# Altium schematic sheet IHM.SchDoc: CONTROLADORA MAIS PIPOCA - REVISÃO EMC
size A3; DocumentNumber: GA0050; SheetNumber: 9; SheetTotal: 17
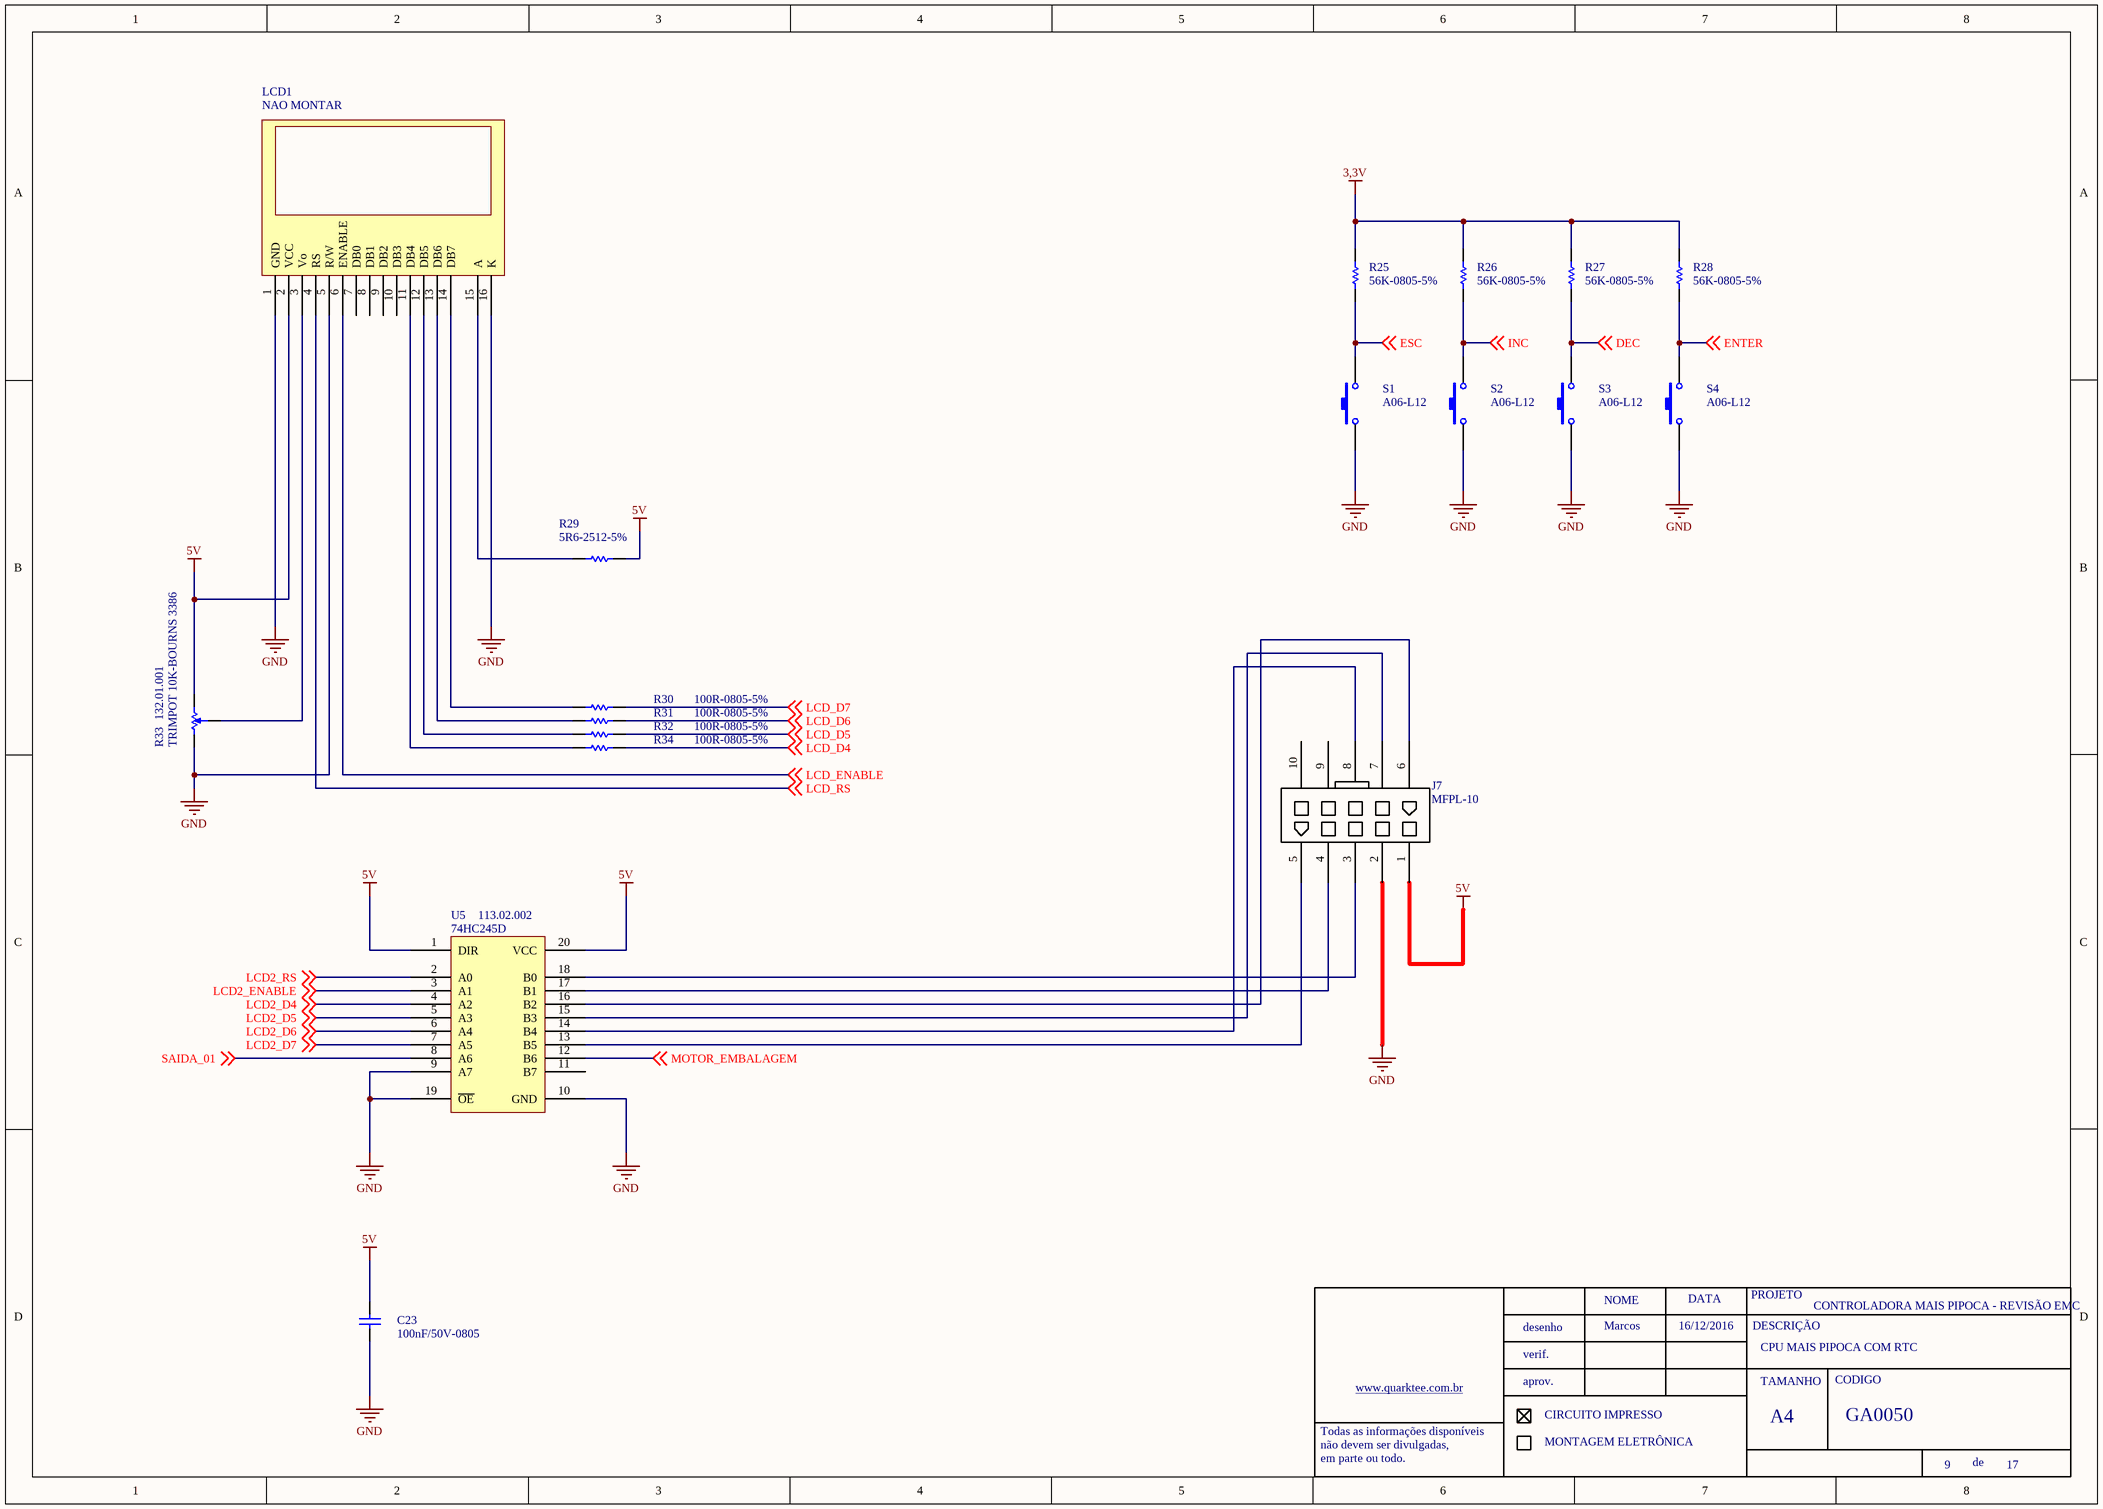
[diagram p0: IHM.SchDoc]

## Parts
C23  100nF/50V-0805  [0805-REVISADO ONDA]
J7  MFPL-10
LCD1  NAO MONTAR  [WH1602B_DS]
R25  56K-0805-5%  [0805-REVISADO ONDA]
R26  56K-0805-5%  [0805-REVISADO ONDA]
R27  56K-0805-5%  [0805-REVISADO ONDA]
R28  56K-0805-5%  [0805-REVISADO ONDA]
R29  5R6-2512-5%  [2512 - REVISADO ONDA]
R30  100R-0805-5%  [0805-REVISADO ONDA]
R31  100R-0805-5%  [0805-REVISADO ONDA]
R32  100R-0805-5%  [0805-REVISADO ONDA]
R33  TRIMPOT 10K-BOURNS 3386  ERP: 132.01.001  [TRIMPOT 3386]
R34  100R-0805-5%  [0805-REVISADO ONDA]
S1  A06-L12  [CHAVE_A06]
S2  A06-L12  [CHAVE_A06]
S3  A06-L12  [CHAVE_A06]
S4  A06-L12  [CHAVE_A06]
U5  74HC245D  ERP: 113.02.002  [SOIC-20]

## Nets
3,3V: R25.1 R26.1 R27.1 R28.1
5V: C23.2 J7.1 LCD1.2(VCC) R29.1 R33.1 U5.1(DIR) U5.20(VCC)
GND: C23.1 J7.2 LCD1.1(GND) LCD1.5(R/W) LCD1.16(K) R33.3 S1.1 S2.1 S3.1 S4.1 U5.9(A7) U5.10(GND) U5.19(~{OE})
DEC: R27.2 S3.2 ; off-sheet DEC
ENTER: R28.2 S4.2 ; off-sheet ENTER
ESC: R25.2 S1.2 ; off-sheet ESC
INC: R26.2 S2.2 ; off-sheet INC
LCD2_D4: U5.4(A2) ; off-sheet LCD2_D4
LCD2_D5: U5.5(A3) ; off-sheet LCD2_D5
LCD2_D6: U5.6(A4) ; off-sheet LCD2_D6
LCD2_D7: U5.7(A5) ; off-sheet LCD2_D7
LCD2_ENABLE: U5.3(A1) ; off-sheet LCD2_ENABLE
LCD2_RS: U5.2(A0) ; off-sheet LCD2_RS
LCD_D4: R34.2 ; off-sheet LCD_D4
LCD_D5: R32.2 ; off-sheet LCD_D5
LCD_D6: R31.2 ; off-sheet LCD_D6
LCD_D7: R30.2 ; off-sheet LCD_D7
LCD_ENABLE: LCD1.6(ENABLE) ; off-sheet LCD_ENABLE
LCD_RS: LCD1.4(RS) ; off-sheet LCD_RS
MOTOR_EMBALAGEM: U5.12(B6) ; off-sheet MOTOR_EMBALAGEM
SAIDA_01: U5.8(A6) ; off-sheet SAIDA_01
NetJ7_3: J7.3 U5.18(B0)
NetJ7_4: J7.4 U5.17(B1)
NetJ7_5: J7.5 U5.13(B5)
NetJ7_6: J7.6 U5.16(B2)
NetJ7_7: J7.7 U5.15(B3)
NetJ7_8: J7.8 U5.14(B4)
NetLCD1_3: LCD1.3(Vo) R33.2
NetLCD1_11: LCD1.11(DB4) R34.1
NetLCD1_12: LCD1.12(DB5) R32.1
NetLCD1_13: LCD1.13(DB6) R31.1
NetLCD1_14: LCD1.14(DB7) R30.1
NetLCD1_15: LCD1.15(A) R29.2

Not connected (* = marked no-connect by the designer): J7 9 10; LCD1 7(DB0) 8(DB1) 9(DB2) 10(DB3); U5 11(B7)

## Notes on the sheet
- Marcos
- 16/12/2016
- CPU MAIS PIPOCA COM RTC

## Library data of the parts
C23 = 100nF/50-0805-NPO
LCD1 = WH1602A
R29 = RES 5R6-CR100: 5R6-CR100
R33 = TRIMPOT 3386 50K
